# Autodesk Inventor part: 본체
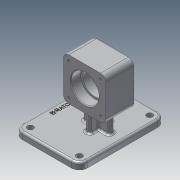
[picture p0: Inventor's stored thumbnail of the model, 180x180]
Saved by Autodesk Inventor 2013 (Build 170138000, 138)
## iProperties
Created: 2020-11
Part Number: 본체
Material: 알루미늄 6061
Document SubType Name: Modeling
Designer: 19
Density: 2.71 g/cm^3
Mass: 686.108 g
Surface Area: 544.314 cm^2
Volume: 253.176 cm^3
Author: 19
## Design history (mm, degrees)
sketch "스케치1"
  geometry: L1 (-32, -32)-(32, -32); L2 (32, -32)-(32, 32); L3 (32, 32)-(-32, 32); L4 (-32, 32)-(-32, -32); L5 (-32, -32)-(32, 32); L6 (32, -32)-(-32, 32); 1 further point
  constraints: 12 end point, 2 midpoint, 2 parallel, 1 horizontal, 1 perpendicular
  dimensions: "d0" = 64 distance of L3.end L2.end; "d1" = 64 distance of L2.end L1.end
extrude "돌출1" new body sketch "스케치1" stored distance "d2" = 42; taper "d3" = 0 deg
sketch "스케치2"
  geometry: C1 r 21 at (0, 0); 1 further point
  constraints: 1 centre point, 1 coincident
  dimensions: "d4" = 42 diameter of C1
extrude "돌출2" cut sketch "스케치2" distance "d5" = 15; taper "d6" = 0 deg
sketch "스케치3"
  geometry: C1 r 21 at (0, 0); 1 further point
  constraints: 1 centre point, 1 coincident
  dimensions: "d7" = 42 diameter of C1
extrude "돌출3" cut sketch "스케치3" distance "d8" = 15; taper "d9" = 0 deg
sketch "스케치4"
  geometry: C1 r 21 at (0, 0) reference; C2 r 18 at (0, 0)
  constraints: 1 centre point, 1 coincident
  dimensions: "d10" = 36 diameter of C2
extrude "돌출4" cut sketch "스케치4" stored distance "d11" = 15; taper "d12" = 0 deg
fillet "모깎기1" dims "d13" = 8
sketch "스케치5"
  geometry: A1 r 8 centre (-24, -24) between (-32, -24) and (-24, -32) reference; A2 r 8 centre (24, -24) between (24, -32) and (32, -24) reference; A3 r 8 centre (24, 24) between (32, 24) and (24, 32) reference; A4 r 8 centre (-24, 24) between (-24, 32) and (-32, 24) reference; 4 further points
  constraints: 4 coincident
hole "구멍1" sketch "스케치5" at (-24, 24), (-24, -24), (24, -24), (24, 24) diameter "d14" = 3.242; stored, may be unused: countersink angle "d18" = 90 deg, drill point angle "d20" = 118 deg; dims "d15" = 8, "d16" = 4, "d17" = 2, "d19" = 10
node "작업 평면1"
sketch "스케치6"
  geometry: L1 (24, -21)-(-24, -21) reference; L2 (-24, 21)-(24, 21) reference; L3 (-32, 21)-(-32, -21) reference; L4 (32, -21)-(32, 21) reference; L5 (62, 65)-(-36, 65); L6 (-36, 65)-(-36, -65); L7 (-36, -65)-(62, -65); L8 (62, -65)-(62, 65); 1 further point
  constraints: 8 end point, 2 parallel, 1 horizontal, 1 perpendicular
  dimensions: "d22" = 98 distance of L7.end L6.end; "d23" = 130 distance of L6.end L5.end; "d24" = 62 distance from line of point (0, 0) L8; "d25" = 65 distance from line of L7 point (0, 0)
extrude "돌출5" join sketch "스케치6" distance "d26" = 10; taper "d27" = 0 deg
fillet "모깎기2" dims "d28" = 12
sketch "스케치7"
  geometry: A1 r 12 centre (-50, 53) between (-50, 65) and (-62, 53) reference; A2 r 12 centre (-50, -53) between (-62, -53) and (-50, -65) reference; A3 r 12 centre (24, -53) between (24, -65) and (36, -53) reference; A4 r 12 centre (24, 53) between (36, 53) and (24, 65) reference; 5 further points
  constraints: 4 coincident
hole "구멍2" sketch "스케치7" at (-50, -53), (24, -53), (24, 53), (-50, 53) diameter "d29" = 9; stored, may be unused: countersink angle "d33" = 90 deg, drill point angle "d35" = 118 deg; dims "d30" = 8, "d31" = 4, "d32" = 2, "d34" = 10
sketch "스케치8"
  geometry: L1 (4, -17)-(-4, -17); L2 (-4, -17)-(-4, 17); L3 (-4, 17)-(4, 17); L4 (4, 17)-(4, -17); L5 (4, -17)-(-4, 17); L6 (-4, -17)-(4, 17); L7 (20, -4)-(-20, -4); L8 (-20, -4)-(-20, 4); L9 (-20, 4)-(20, 4); L10 (20, 4)-(20, -4); L11 (20, -4)-(-20, 4); L12 (-20, -4)-(20, 4); 1 further point
  constraints: 24 end point, 4 midpoint, 4 parallel, 2 horizontal, 2 perpendicular
  dimensions: "d36" = 8 distance of L2.end L3.end; "d37" = 34 distance of L1.end L2.end; "d38" = 40 distance of L8.end L9.end; "d39" = 8 distance of L7.end L8.end
extrude "돌출6" join sketch "스케치8" stored distance "d40" = 0; taper "d41" = 0 deg
fillet "모깎기3" dims "d42" = 3
fillet "모깎기4" dims "d43" = 3
sketch "스케치9"
  geometry: L1 (-62, 53)-(-62, -53) reference; 2 further points
  constraints: 1 horizontal alignment, 1 other
  dimensions: "d44" = 10 distance from line of L1 point (-52, 0)
feature "엠보싱1" sketch "스케치9" dims "d0" = 64, "d1" = 64, "d12" = 0, "d45" = 0.5, "d46" = 0
fillet "모깎기5" dims "d47" = 3
fillet "모깎기6" dims "d48" = 0.3
chamfer "모따기1" distance "d49" = 1; stored, may be unused: second distance "d50" = 2, angle "d51" = 45 deg
node "솔리드1"
mirror "대칭1"
